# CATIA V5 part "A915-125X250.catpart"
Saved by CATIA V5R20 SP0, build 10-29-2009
Part number: A915-125X250
Source: Unknown
Property "A": "75.000"
Property "ARTICLENO": "A915-125X250"
Property "BOMINFO": "A915-125X250"
Property "CODE": "A915-125X250"
Property "CREATOR": "CADENAS GmbH"
Property "D": "13.500"
Property "D1": "20.000"
Property "FORM": "C"
Property "L": "250.000"
Property "L1": "40.000"
Property "L2": "170.000"
Property "LINA": "A915-125X250"
Property "NB": "A915-125X250"
Property "NBSYN": "$CODE."
Property "NN": "A915"
Property "NT": "VDI 3357 Wear Plates, steel"
Property "SCREW": "M12x25"
Property "SUPPLIER": "CF"
Property "T": "13.000"
Property "W": "125.000"
Bounding box of the stored display mesh (mm): x 0 to 20, y 0 to 250, z -62.5 to 62.5
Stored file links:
  C:\Users\borellobunino\Desktop\3D X SITO CF\A915\GSB_OILLESS_G22501125250\CATIAV5\A915-125X250.catpart
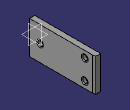
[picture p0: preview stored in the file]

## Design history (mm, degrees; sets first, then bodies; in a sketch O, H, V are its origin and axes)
Body1 "Geometry.1" (main body)
  Solid1 "A915-125X250.catpart": solid without history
